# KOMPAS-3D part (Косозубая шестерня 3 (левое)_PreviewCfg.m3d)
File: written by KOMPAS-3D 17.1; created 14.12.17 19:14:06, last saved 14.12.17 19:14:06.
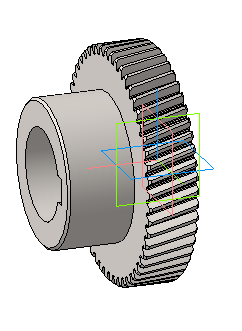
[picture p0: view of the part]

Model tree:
1. Операция без истории:1  (labels: Косозубая шестерня 3 (левое)_PreviewCfg)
